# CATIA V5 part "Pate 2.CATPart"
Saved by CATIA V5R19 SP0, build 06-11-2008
Part number: Part2
Bounding box of the stored display mesh (mm): x -10 to 10, y -43.875 to 10, z -10 to 43.912
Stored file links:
  D:\thinkmotion-MPB\Dropbox\CIAO82010_JCF\BAUVIN\554_bauvin\Pate 2.CATPart
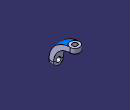
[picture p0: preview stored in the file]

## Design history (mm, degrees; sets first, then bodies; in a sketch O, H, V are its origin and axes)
Line1: type Normal, RefPoint Point2, RefSkin face of Pocket3, Start 0, End 20
Line2 to Line4: stored without definition
Body1 (main body)
  Sketch1 on yz-plane, origin (0, 0, 0), H (0, 1, 0), V (0, 0, 1)
    arc A1 centre (0, 0) radius 45 from (0, 45) to (-45, 0) ccw
    point P1 (-45, 0)
    point P2 (0, 45)
    line L1 (0, 45) -> (0, 0)
    line L2 (0, 0) -> (-45, 0)
    radius A1 = 45
    coincidence: P1 H, P2 V
    vertical: L1 V
    horizontal: L2 H
  Shaft1: profile Sketch1, axis Sketch1.L2, angle 90, second angle 90
  Sketch2 on face of Shaft1 from Sketch1.L1, origin (0, 0, 0), H (-1, 0, 0), V (0, 0, 1)
    line L1 (10, 68.2634) -> (99.7654, 68.2634)
    line L2 (99.7654, 68.2634) -> (99.7654, 0)
    line L3 (99.7654, 0) -> (10, 0)
    line L4 (10, 0) -> (10, 68.2634)
    point P3 (99.7654, 0)
    line L5 (-99.7654, 68.2634) -> (-10, 68.2634)
    line L6 (-10, 0) -> (-99.7654, 0)
    line L7 (-10, 68.2634) -> (-10, 0)
    line L8 (-99.7654, 0) -> (-99.7654, 68.2634)
    point P5 (-10, 0)
    distance L7 L4 = 20
    horizontal: L1 H, L3 H, L5 H, L6 H
    vertical: L2 V, L4 V, L7 V, L8 V
    coincidence: P3 H, P5 H, L1 L5
    symmetry: L7 L4 V, L8 L2 V
  Pocket1: profile Sketch2, direction (0, -1, 0), through (limit type 3)
  Sketch3 on face of Pocket1 from Sketch2.L7, origin (10, 0, 0), H (0, 1, 0), V (0, 0, 1)
    arc A1 centre (0, 0) radius 33.8748 from (0, 33.8748) to (-33.8748, 0) ccw
    point P1 (-33.8748, 0)
    point P2 (0, 33.8748)
    reference projected point E1 (0, 43.8748) from vertex [face of Shaft1 from Sketch1.L1 | face of Shaft1 from Sketch1.A1 | face of Pocket1 from Sketch2.L7]
    line L1 (0, 33.8748) -> (0, 0)
    line L2 (0, 0) -> (-33.8748, 0)
    distance E1 P2 = 10
    coincidence: P1 H, P2 V
    vertical: L1 V
    horizontal: L2 H
  Pocket2: profile Sketch3, direction (1, 0, 0), length 20, mirrored extent
  Plane1: type Angle, RefPlane face of Shaft1 from Sketch1.L1, Direction edge [face of Shaft1 from Sketch1.L1 | face of Pocket2 from Sketch3.A1], Angle 90
  Plane2: type Angle, RefPlane face of Shaft1, Direction edge [face of Pocket2 from Sketch3.A1 | face of Shaft1], Angle 90
  Sketch4 on Plane1, origin (0, 0, 33.8748), H (1, 0, 0), V (0, -1, 0)
    arc A1 centre (0, 0) radius 10 from (-10, 0) to (10, 0) ccw
    point P1 (10, 0)
    point P2 (-10, 0)
    line L1 (-10, 0) -> (10, 0)
    reference projected point E1 (10, 0) from vertex [face of Pocket1 from Sketch2.L7 | face of Pocket2 from Sketch3.A1 | face of Shaft1 from Sketch1.L1]
    coincidence: P1 H, P2 H, P1 E1
    horizontal: L1 H
  Pad1: profile Sketch4, direction (0, 0, 1), length 10
  Sketch5 on Plane2, origin (0, -33.8748, 0), H (1, 0, 0), V (0, 0, 1)
    arc A1 centre (0, 0) radius 10 from (-10, 0) to (10, 0) ccw
    point P1 (10, 0)
    point P2 (-10, 0)
    line L1 (-10, 0) -> (10, 0)
    reference projected point E1 (-10, 0) from vertex [face of Shaft1 from Sketch1.A1 | face of Shaft1 | face of Pocket1 from Sketch2.L4]
    coincidence: P1 H, P2 H, P2 E1
    horizontal: L1 H
  Pad2: profile Sketch5, direction (0, -1, 0), length 10
  Sketch6 on yz-plane, origin (0, 0, 0), H (0, 1, 0), V (0, 0, 1)
    line L1 (-54.803, 11.9858) -> (-43.8748, 11.9858)
    line L2 (-43.8748, 11.9858) -> (-43.8748, -14.6225)
    line L3 (-43.8748, -14.6225) -> (-54.803, -14.6225)
    line L4 (-54.803, -14.6225) -> (-54.803, 11.9858)
    line L5 (-9.8126, 53.061) -> (18.2204, 53.061)
    line L6 (18.2204, 53.061) -> (18.2204, 43.8748)
    line L7 (18.2204, 43.8748) -> (-9.8126, 43.8748)
    line L8 (-9.8126, 43.8748) -> (-9.8126, 53.061)
    reference projected line E1 (10, 43.8748) -> (0, 43.8748) from edge [end face of Pad1 | face of Pad1 from Sketch4.A1]
    reference projected line E2 (-43.8748, -10) -> (-43.8748, 0) from edge [face of Pad2 from Sketch5.A1 | end face of Pad2]
    horizontal: L1 H, L3 H, L5 H, L7 H
    vertical: L2 V, L4 V, L6 V, L8 V
    coincidence: L7 E1, L2 E2
  Pocket3: profile Sketch6, direction (-1, 0, 0), length 10, mirrored extent
  Sketch7 on face of Pocket3, origin (0, 0, 43.8748), H (1, 0, 0), V (0, 1, 0)
    circle A1 centre (0, 0) radius 5
    radius A1 = 5
  Pocket4: profile Sketch7, direction (0, 0, -1), through (limit type 3)
  Sketch8 on face of Pocket3, origin (0, -43.8748, 0), H (1, 0, 0), V (0, 0, 1)
    circle A1 centre (0, 0) radius 5
    radius A1 = 5
  Pocket5: profile Sketch8, direction (0, 1, 0), through (limit type 3)
  Point1: type Center, Curve edge [face of Pocket3 | face of Pocket4 from Sketch7.A1]
  Point2: type Center, Curve edge [face of Pocket3 | face of Pocket5 from Sketch8.A1]
  Line5: type Normal, RefPoint Point1, RefSkin face of Pocket3, Start 0, End 20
